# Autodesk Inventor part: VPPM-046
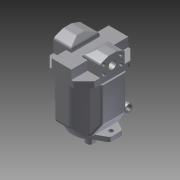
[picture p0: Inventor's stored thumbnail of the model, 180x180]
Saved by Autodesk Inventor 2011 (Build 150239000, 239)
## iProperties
Created: 2012-02
Part Number: VPPM-046
Document SubType Name: Modeling
Designer: khramov
Density: 1 g/cm^3
Стандарт преобразования: STEP AP203
Имя файла: VPPM-046.stp
Препроцессор: Mechanical Desktop 2011
Постпроцессор: Build: 239, Release: 2011 RTM - Date: Wed 02/17/2010
Отправленные единицы: миллиметр
Неопределенность: 1.0000000000000002e-06
Author: khramov
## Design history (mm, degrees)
feature "БазТело1"
sketch "Эскиз1"
  geometry: C1 r 50 at (0, 0); A1 r 60 centre (0, 0) between (-29.349, -52.332) and (29.349, -52.332) reference
  constraints: 1 centre point, 1 coincident
  dimensions: "d0" = 100 diameter of C1
extrude "Выдавливание1" join sketch "Эскиз1" distance "d1" = 9; taper "d2" = 0 deg
sketch "Эскиз2"
  geometry: C1 r 50 at (0, 0) reference; C2 r 12.5 at (0, 0)
  constraints: 1 centre point, 1 coincident
  dimensions: "d3" = 25 diameter of C2
extrude "Выдавливание2" join sketch "Эскиз2" distance "d4" = 42; taper "d5" = 0 deg
sketch "Эскиз3"
  geometry: L1 (87, 20)-(87, -20) reference; L2 (-87, -20)-(-87, 20) reference; L3 (-87, 0)-(87, 0); L4 (87, -20)-(87, 20) reference; C1 r 7 at (-70, 0); C2 r 7 at (70, 0)
  constraints: 2 centre point, 2 end point, 2 midpoint, 2 point on line
  dimensions: "d6" = 14 diameter of C1; "d7" = 14 diameter of C2; "d8" = 140 distance of C1.centre C2.centre; "d9" = 174 distance between parallel lines of L1 L2 (derived); "d10" = 17 distance from line of L2 C1.centre
extrude "Выдавливание3" cut sketch "Эскиз3" distance "d11" = 15; taper "d12" = 0 deg
sketch "Эскиз4"
  geometry: L1 (-55, -29)-(-4.349, -29) reference; L2 (-29.674, -29)-(-60.703, 19.031); L3 (-60.703, 19.031)-(-62.752, -29); L4 (-62.752, -29)-(-29.674, -29); L5 (37.5, -95)-(12.5, -95) reference; L6 (25, -95)-(25, 273.459); L7 (110.703, 19.031)-(112.752, -29); L8 (79.674, -29)-(110.703, 19.031); L9 (112.752, -29)-(79.674, -29); L10 (88, -29)-(102, -29) reference; 2 further points
  constraints: 14 end point, 4 symmetric about line, 2 collinear, 2 midpoint, 1 perpendicular
extrude "Выдавливание4" cut sketch "Эскиз4" distance "d13" = 300; taper "d14" = 0 deg
sketch "Эскиз5"
  geometry: L1 (-220, 29.502)-(-220, 54.502) reference; L2 (-220, 42.002)-(139.553, 42.002); L3 (-169, 94.334)-(-169, 62.002) reference; C1 r 19.05 at (37, 42.002); 1 further point
  constraints: 2 end point, 1 centre point, 1 midpoint, 1 perpendicular, 1 point on line
  dimensions: "d15" = 38.1 diameter of C1; "d16" = 206 distance from line of C1.centre L3
extrude "Выдавливание5" cut sketch "Эскиз5" distance "d17" = 50; taper "d18" = 0 deg
sketch "Эскиз6"
  geometry: L1 (19.15, 77.002)-(54.85, 77.002); L2 (54.85, 77.002)-(54.85, 7.002); L3 (54.85, 7.002)-(19.15, 7.002); L4 (19.15, 7.002)-(19.15, 77.002); L5 (37, 77.002)-(37, 42.002); L6 (37, 42.002)-(19.15, 42.002); C1 r 19.05 at (37, 42.002) reference; 5 further points
  constraints: 12 end point, 4 coincident, 2 horizontal, 2 midpoint, 2 parallel, 1 perpendicular, 1 vertical
  dimensions: "d22" = 70 distance of L1.end L2.end; "d23" = 35.7 distance of L1.start L1.end
hole "Отверстие1" sketch "Эскиз6" at (54.85, 77.002), (19.15, 77.002), (19.15, 7.002), (54.85, 7.002) diameter "d24" = 10.106; stored, may be unused: countersink angle "d28" = 90 deg, drill point angle "d30" = 118 deg; dims "d25" = 26, "d26" = 12.5, "d27" = 2, "d29" = 30
sketch "Эскиз7"
  geometry: L1 (220, 54.502)-(220, 29.502) reference; L2 (220, 42.002)-(-127.024, 42.002); L3 (169, 22.002)-(169, 62.002) reference; C1 r 12.7 at (-37, 42.002); 1 further point
  constraints: 2 end point, 1 centre point, 1 midpoint, 1 perpendicular, 1 point on line
  dimensions: "d31" = 206 distance from line of L3 C1.centre; "d32" = 25.4 diameter of C1
extrude "Выдавливание6" cut sketch "Эскиз7" distance "d33" = 40; taper "d34" = 0 deg
sketch "Эскиз8"
  geometry: L1 (-50.85, 70.552)-(-23.15, 70.552); L2 (-23.15, 70.552)-(-23.15, 13.452); L3 (-23.15, 13.452)-(-50.85, 13.452); L4 (-50.85, 13.452)-(-50.85, 70.552); L5 (-37, 70.552)-(-37, 42.002); L6 (-37, 42.002)-(-50.85, 42.002); C1 r 12.7 at (-37, 42.002) reference; 5 further points
  constraints: 12 end point, 4 coincident, 2 horizontal, 2 midpoint, 2 parallel, 1 perpendicular, 1 vertical
  dimensions: "d35" = 27.7 distance of L1.start L1.end; "d36" = 57.1 distance of L1.end L2.end
hole "Отверстие2" sketch "Эскиз8" at (-50.85, 70.552), (-23.15, 70.552), (-23.15, 13.452), (-50.85, 13.452) diameter "d37" = 10.106; stored, may be unused: countersink angle "d41" = 90 deg, drill point angle "d43" = 118 deg; dims "d38" = 26, "d39" = 12.5, "d40" = 2, "d42" = 30
fillet "Сопряжение1" dims "d51" = 10
fillet "Сопряжение2" dims "d52" = 10
fillet "Сопряжение3" dims "d53" = 10
fillet "Сопряжение4" dims "d54" = 10
fillet "Сопряжение5" dims "d55" = 5
fillet "Сопряжение6" dims "d56" = 15
fillet "Сопряжение7" dims "d57" = 10
sketch "Эскиз11"
  geometry: L1 (7.907, 98)-(19.177, 98); L2 (19.177, 98)-(19.177, 89.95); L3 (19.177, 89.95)-(7.907, 89.95); L4 (7.907, 89.95)-(7.907, 98); 1 further point
  constraints: 2 other
extrude "Выдавливание7" cut sketch "Эскиз11" distance "d58" = 0.5; taper "d59" = 0 deg
sketch "Эскиз12"
  geometry: L1 (-15.049, 97.34)-(-3.071, 97.34); L2 (-3.071, 97.34)-(-3.071, 90.005); L3 (-3.071, 90.005)-(-15.049, 90.005); L4 (-15.049, 90.005)-(-15.049, 97.34); 1 further point
  constraints: 2 other
extrude "Выдавливание8" cut sketch "Эскиз12" distance "d60" = 0.5; taper "d61" = 0 deg
sketch "Эскиз13"
  geometry: L1 (-111.847, 65.996)-(0, 65.996) reference; L2 (57.153, 55.863)-(57.153, 85.33) reference; L3 (108.153, 45.498)-(108.153, 20.498) reference; L4 (108.153, 32.998)-(24.909, 32.998); C1 r 13 at (17.153, 101.328); 4 further points; 1 other entity
  constraints: 2 end point, 1 centre point, 1 midpoint, 1 perpendicular, 1 other
  dimensions: "d62" = 40 distance from line of C1.centre L2; "d63" = 35.33241 distance from line of L1 point (17.153, 101.328) (derived); "d64" = 35.332 distance from line of L1 C1.centre; "d65" = 26 diameter of C1
extrude "Выдавливание9" join sketch "Эскиз13" distance "d66" = 60; taper "d67" = 0 deg
sketch "Эскиз14"
  geometry: C1 r 13 at (0, 0) reference; 1 further point
extrude "Выдавливание10" cut sketch "Эскиз14" distance "d68" = 20; taper "d69" = 0 deg
sketch "Эскиз15"
  geometry: C1 r 13 at (0, 0) reference; 2 further points
  constraints: 1 coincident
hole "Отверстие4" sketch "Эскиз15" at (0, 0) diameter "d70" = 18.631; stored, may be unused: countersink angle "d74" = 90 deg, drill point angle "d76" = 118 deg; dims "d71" = 22, "d72" = 4, "d73" = 2, "d75" = 30
node "7DFA"
